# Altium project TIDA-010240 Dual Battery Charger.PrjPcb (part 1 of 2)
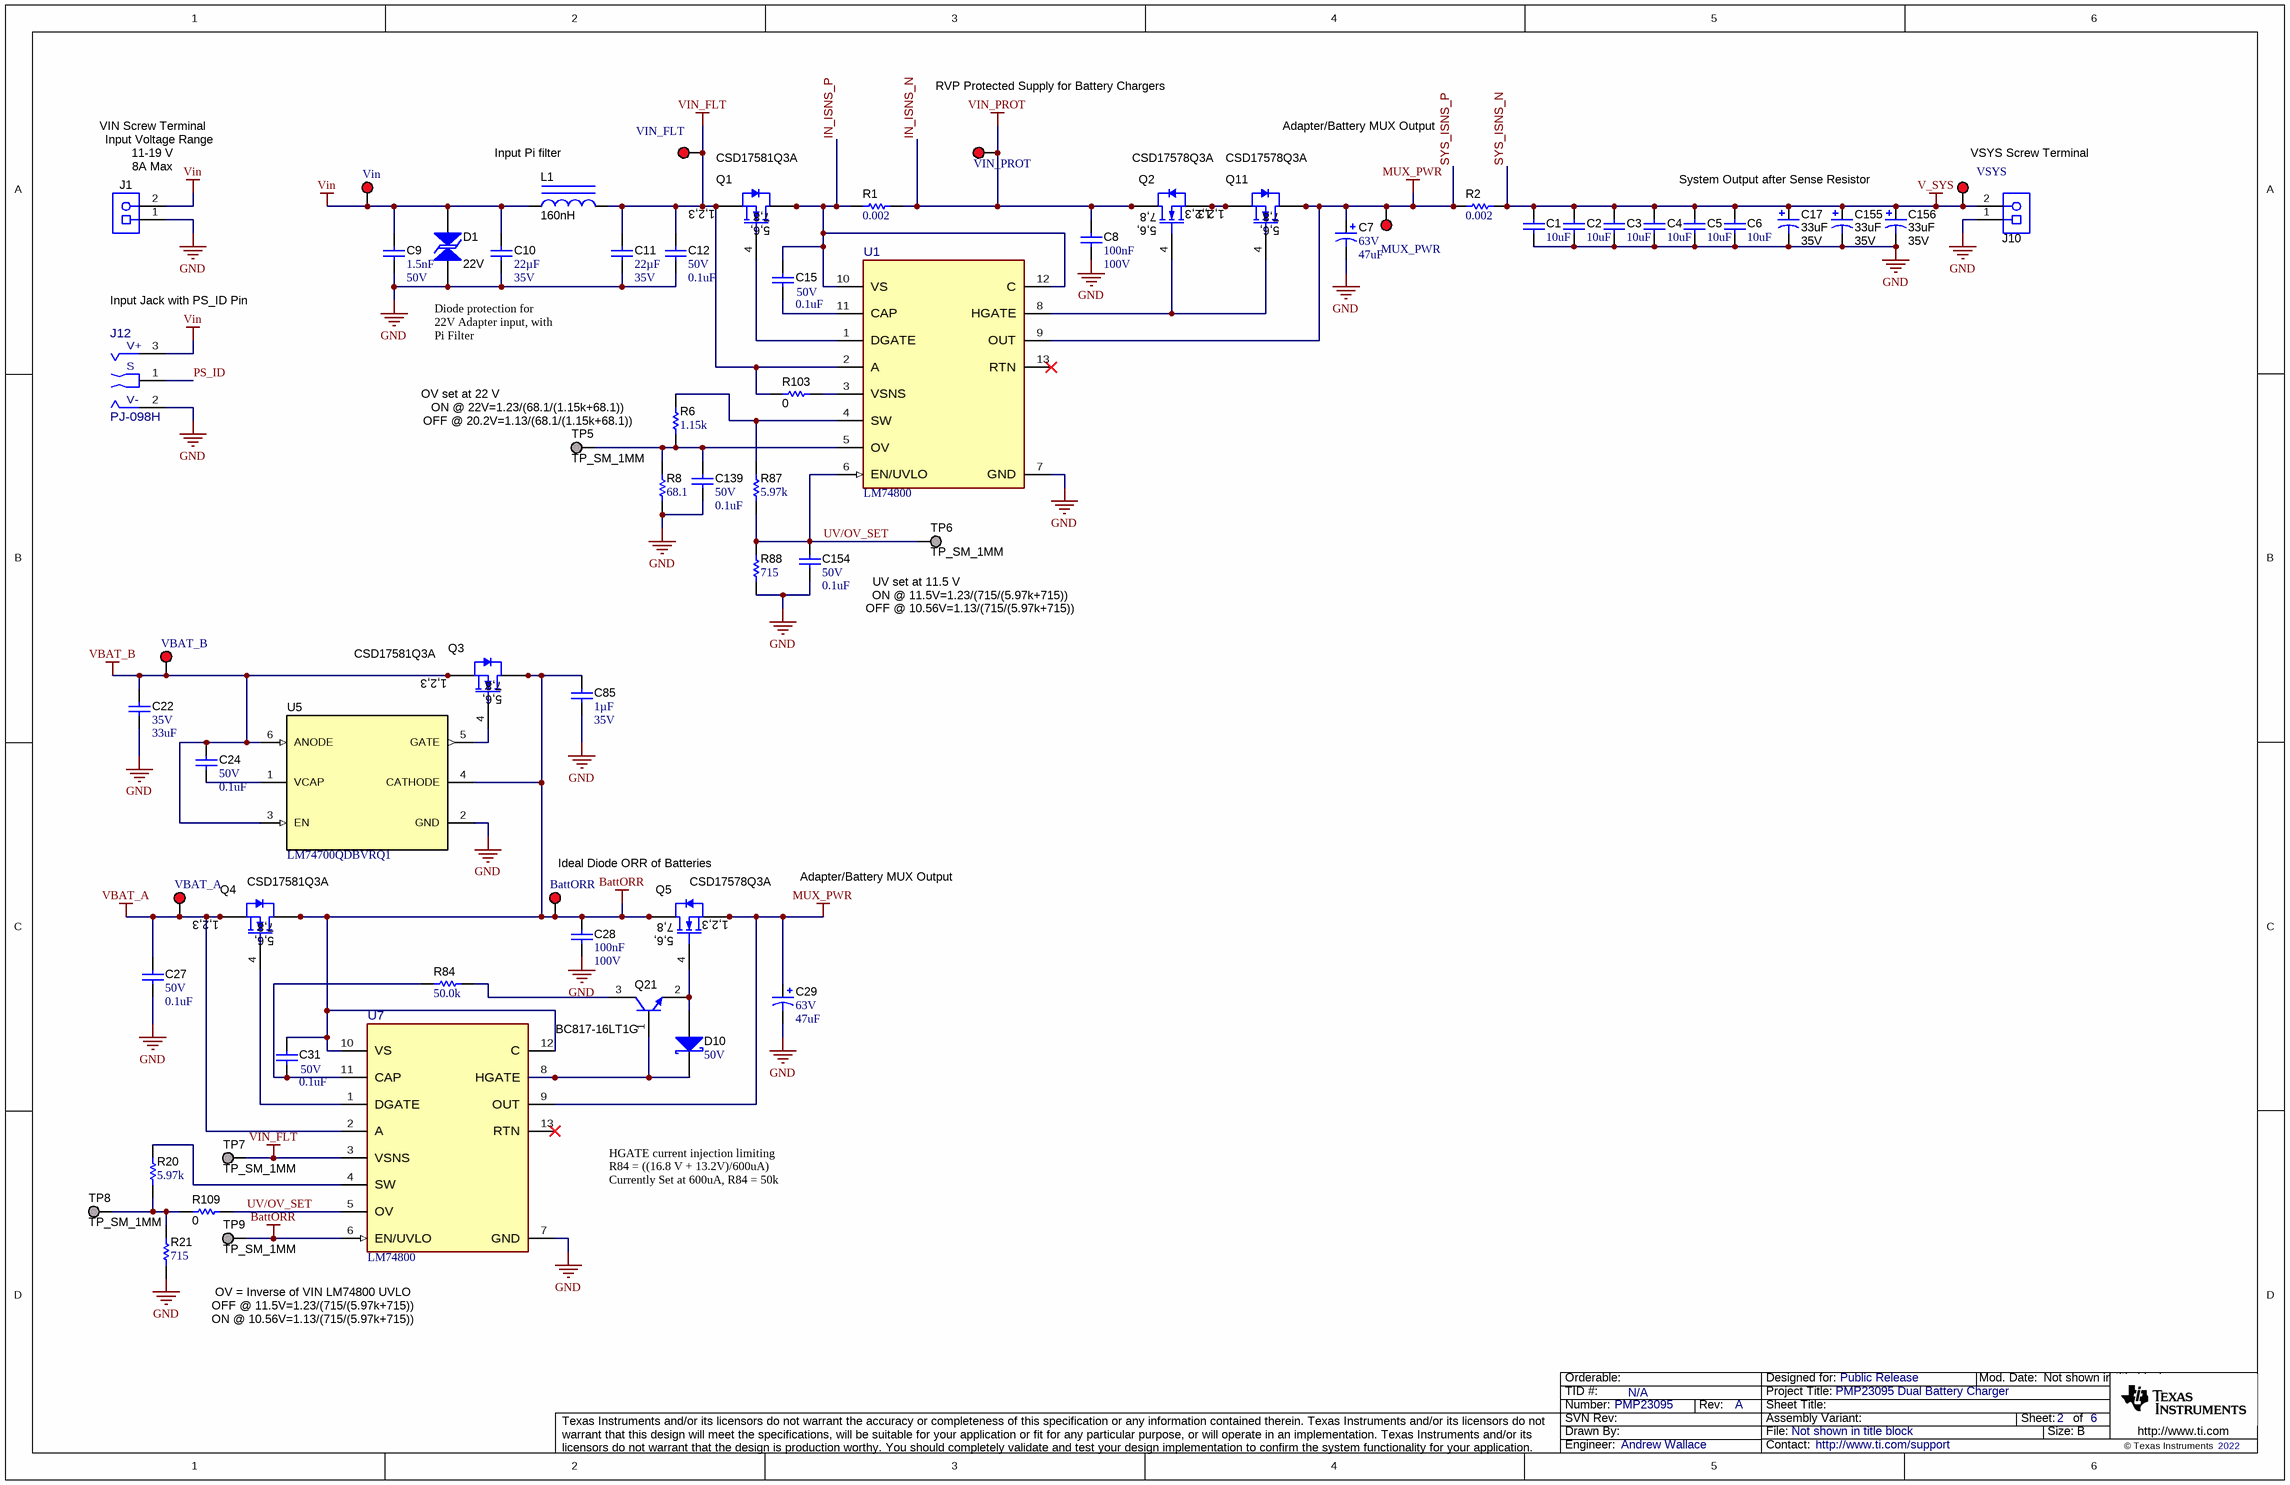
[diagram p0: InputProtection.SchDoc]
TID: N/A; TechSupport: http://www.ti.com/support; SCH_Rev: A; PRJ_Title: PMP23095 Dual Battery Charger; PRJ_Number: PMP23095; PRJ_Engineer: Andrew Wallace; PRJ_Customer: Public Release; PCB_Rev: A; PCB_Layout: Andrew Wallace; CopyrightYear: 2022
6 sheets, 371 parts. Net scope: global (net labels, ports and power ports of the same name join across sheets).
Board file: PCB_Project.PcbDoc
Sheets:
  InputProtection.SchDoc
  PCB_Project_Hardware.SchDoc
  MSP.SchDoc
  BQ25731_A.SchDoc
  BQ25731_B.SchDoc
  Sensing.SchDoc

## Sheet InputProtection.SchDoc
size 431 x 279 mm; Date: Not shown in title block; ApprovedBy: Not shown in title block; CheckedBy: Not shown in title block; Author: Not shown in title block; CompanyName: Not shown in title block; Engineer: Not shown in title block; Organization: Not shown in title block; Address1: Not shown in title block; Address2: Not shown in title block; Address3: Not shown in title block; Address4: Not shown in title block; DocumentNumber: 2; Revision: Use project parameter SCH_Rev; SheetNumber: 2; SheetTotal: 6; PageSetup: Record=PageOptions¦CenterHorizontal=True¦CenterVertical=True¦PrintScale=1.00¦XCorrection=1.00¦YCorrection=1.00¦PrintKind=0¦BorderSize=5000000¦LeftOffset=0¦BottomOffset=0¦Orientation=2¦PaperLength=1000¦PaperWidth=1000¦Scale=100¦PaperSource=15¦PrintQuality=600¦MediaType=1¦DitherType=10¦PaperKind=Letter¦PrintScaleMode=1

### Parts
BattORR  5010  [Keystone5010]  (value not drawn)
C1  ValueDisplayed: 10uF  [0805L]  (hidden comment: GRM21BR6YA106KE43L)
C2  ValueDisplayed: 10uF  [0805L]  (hidden comment: GRM21BR6YA106KE43L)
C3  ValueDisplayed: 10uF  [0805L]  (hidden comment: GRM21BR6YA106KE43L)
C4  ValueDisplayed: 10uF  [0805L]  (hidden comment: GRM21BR6YA106KE43L)
C5  ValueDisplayed: 10uF  [0805L]  (hidden comment: GRM21BR6YA106KE43L)
C6  ValueDisplayed: 10uF  [0805L]  (hidden comment: GRM21BR6YA106KE43L)
C7  VDC_V: 63V  ValueDisplayed: 47uF  [CAPSMT_62_HA0]  (hidden comment: EMVA630ADA470MHA0G)
C8  Cap_F: 100nF  VDC_V: 100V  [0603]  (hidden comment: GRM188R72A104KA35J)
C9  Cap_F: 1.5nF  VDC_V: 50V  [0603]  (hidden comment: GRM188R71H152KA01D)
C10  Cap_F: 22µF  VDC_V: 35V  [0805_HV]  (hidden comment: NMC0805X5R226M35TRPLPF)
C11  Cap_F: 22µF  VDC_V: 35V  [0805_HV]  (hidden comment: NMC0805X5R226M35TRPLPF)
C12  VDC_V: 50V  ValueDisplayed: 0.1uF  [0402]  (hidden comment: GCM155R71H104KE02D)
C15  VDC_V: 50V  ValueDisplayed: 0.1uF  [0402]  (hidden comment: GCM155R71H104KE02D)
C17  ValueDisplayed: 33uF  VDC_V: 35V  [7343-31]  (hidden comment: T521D336M035ATE065)
C22  VDC_V: 35V  ValueDisplayed: 33uF  [KCM55W]  (hidden comment: KCM55WR7YA336MH01K)
C24  VDC_V: 50V  ValueDisplayed: 0.1uF  [0402]  (hidden comment: GCM155R71H104KE02D)
C27  VDC_V: 50V  ValueDisplayed: 0.1uF  [0402]  (hidden comment: GCM155R71H104KE02D)
C28  Cap_F: 100nF  VDC_V: 100V  [0603]  (hidden comment: GRM188R72A104KA35J)
C29  VDC_V: 63V  ValueDisplayed: 47uF  [CAPSMT_62_HA0]  (hidden comment: EMVA630ADA470MHA0G)
C31  VDC_V: 50V  ValueDisplayed: 0.1uF  [0402]  (hidden comment: GCM155R71H104KE02D)
C85  Cap_F: 1µF  VDC_V: 35V  [0603]  (hidden comment: CGA3E1X7R1V105K080AC)
C139  VDC_V: 50V  ValueDisplayed: 0.1uF  [0402]  (hidden comment: GCM155R71H104KE02D)
C154  VDC_V: 50V  ValueDisplayed: 0.1uF  [0402]  (hidden comment: GCM155R71H104KE02D)
C155  ValueDisplayed: 33uF  VDC_V: 35V  [7343-31]  (hidden comment: T521D336M035ATE065)
C156  ValueDisplayed: 33uF  VDC_V: 35V  [7343-31]  (hidden comment: T521D336M035ATE065)
D1  value 22V  [SMC_Bi]  (hidden comment: SMCJ22CA-TR)
D10  value 50V  [SMA]  (hidden comment: B150-13-F)
J1  Receptacle_2x1  [On-Shore_ED120_2DS]  (value not drawn)
J10  Receptacle_2x1  [On-Shore_ED120_2DS]  (value not drawn)
J12  PJ-098H  [FP-PJ-098H_PTH_CONN_8MM0_12MM0-MFG]
L1  ValueDisplayed: 160nH  [WE-HCM_7070]  (hidden comment: 744307016)
MUX_PWR  5010  [Keystone5010]  (value not drawn)
Q1  CSD17581Q3A  [DNH0008A]
Q2  CSD17578Q3A  [DNH0008A]
Q3  CSD17581Q3A  [DNH0008A]
Q4  CSD17581Q3A  [DNH0008A]
Q5  CSD17578Q3A  [DNH0008A]
Q11  CSD17578Q3A  [DNH0008A]
Q21  BC817-16LT1G  [SOT-23]
R1  ValueDisplayed: 0.002  [1206]  (hidden comment: PMR18EZPFV2L00)
R2  ValueDisplayed: 0.002  [1206]  (hidden comment: PMR18EZPFV2L00)
R6  ValueDisplayed: 1.15k  [0603]  (hidden comment: RT0603BRD071K15L)
R8  ValueDisplayed: 68.1  [0603]  (hidden comment: CRCW060368R1FKEA)
R20  ValueDisplayed: 5.97k  [0603]  (hidden comment: RT0603DRE075K97L)
R21  ValueDisplayed: 715  [0603]  (hidden comment: RC0603FR-07715RL)
R84  ValueDisplayed: 50.0k  [0603]  (hidden comment: RT0603DRE0753KL)
R87  ValueDisplayed: 5.97k  [0603]  (hidden comment: RT0603DRE075K97L)
R88  ValueDisplayed: 715  [0603]  (hidden comment: RC0603FR-07715RL)
R103  ValueDisplayed: 0  [0603]  (hidden comment: RMCF0603ZT0R00)
R109  ValueDisplayed: 0  [0603]  (hidden comment: RMCF0603ZT0R00)
TP5  TP_SM_1MM  [TP_SM_1MM]  (no BOM)
TP6  TP_SM_1MM  [TP_SM_1MM]  (no BOM)
TP7  TP_SM_1MM  [TP_SM_1MM]  (no BOM)
TP8  TP_SM_1MM  [TP_SM_1MM]  (no BOM)
TP9  TP_SM_1MM  [TP_SM_1MM]  (no BOM)
U1  LM74800  [DRR0012E-MFG]
U5  LM74700QDBVRQ1  [DBV0006A_N]
U7  LM74800  [DRR0012E-MFG]
VBAT_A  5010  [Keystone5010]  (value not drawn)
VBAT_B  5010  [Keystone5010]  (value not drawn)
Vin  5010  [Keystone5010]  (value not drawn)
VIN_FLT  5010  [Keystone5010]  (value not drawn)
VIN_PROT  5010  [Keystone5010]  (value not drawn)
VSYS  5010  [Keystone5010]  (value not drawn)

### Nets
BattORR: BattORR.1 C28.1 C31.1 C85.2 Q3.5(D) Q3.6(D) Q3.7(D) Q3.8(D) Q3.9(D) Q4.5(D) Q4.6(D) Q4.7(D) Q4.8(D) Q4.9(D) Q5.5(D) Q5.6(D) Q5.7(D) Q5.8(D) Q5.9(D) TP9.1 U5.4(CATHODE) U7.6(EN/UVLO) U7.10(VS) U7.12(C)
GND: C1.2 C2.2 C3.2 C4.2 C5.2 C6.2 C7.2(-) C8.2 C9.2 C10.2 C11.2 C12.2 C17.2(-) C22.2 C27.2 C28.2 C29.2(-) C85.1 C139.2 C154.2 C155.2(-) C156.2(-) D1.1 J1.1 J10.1 J12.2(V-) R8.1 R21.1 R88.1 U1.7(GND) U5.2(GND) U7.7(GND)
IN_ISNS_N: C8.1 Q2.5(D) Q2.6(D) Q2.7(D) Q2.8(D) Q2.9(D) R1.1 VIN_PROT.1  [also labelled VIN_PROT]
SYS_ISNS_N: C1.1 C2.1 C3.1 C4.1 C5.1 C6.1 C17.1(+) C155.1(+) C156.1(+) J10.2 R2.1 VSYS.1  [also labelled V_SYS]
SYS_ISNS_P: C7.1(+) C29.1(+) MUX_PWR.1 Q5.1(S) Q5.2(S) Q5.3(S) Q11.5(D) Q11.6(D) Q11.7(D) Q11.8(D) Q11.9(D) R2.2 U1.9(OUT) U7.9(OUT)  [also labelled MUX_PWR]
VBAT_A: C27.1 Q4.1(S) Q4.2(S) Q4.3(S) U7.2(A) VBAT_A.1
VBAT_B: C22.1 C24.1 Q3.1(S) Q3.2(S) Q3.3(S) U5.3(EN) U5.6(ANODE) VBAT_B.1
Vin: C9.1 C10.1 D1.2 J1.2 J12.3(V+) L1.1 Vin.1
VIN_FLT: C11.1 C12.1 L1.2 Q1.1(S) Q1.2(S) Q1.3(S) R103.1 TP7.1 U1.2(A) U7.3(VSNS) VIN_FLT.1
IN_ISNS_P: C15.1 Q1.5(D) Q1.6(D) Q1.7(D) Q1.8(D) Q1.9(D) R1.2 U1.10(VS) U1.12(C)
PS_ID: J12.1(S)
UV/OV_SET: C154.1 R87.1 R88.2 R109.2 TP6.1 U1.6(EN/UVLO) U7.5(OV)
NetC15_2: C15.2 U1.11(CAP)
NetC24_2: C24.2 U5.1(VCAP)
NetC31_2: C31.2 R84.1 U7.11(CAP)
NetC139_1: C139.1 R6.1 R8.2 TP5.1 U1.5(OV)
NetD10_1: D10.1(K) Q21.1(B) U7.8(HGATE)
NetD10_2: D10.2(A) Q5.4(G) Q21.2(E)
NetQ1_4: Q1.4(G) U1.1(DGATE)
NetQ2_1: Q2.1(S) Q2.2(S) Q2.3(S) Q11.1(S) Q11.2(S) Q11.3(S)
NetQ2_4: Q2.4(G) Q11.4(G) U1.8(HGATE)
NetQ3_4: Q3.4(G) U5.5(GATE)
NetQ4_4: Q4.4(G) U7.1(DGATE)
NetQ21_3: Q21.3(C) R84.2
NetR6_2: R6.2 R87.2 U1.4(SW)
NetR20_1: R20.1 R21.2 R109.1 TP8.1
NetR20_2: R20.2 U7.4(SW)
NetR103_2: R103.2 U1.3(VSNS)

Not connected (* = marked no-connect by the designer): U1 13(RTN)*; U7 13(RTN)*

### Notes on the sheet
- RVP Protected Supply for Battery Chargers
- (near J1) 11-19 V
- (near J1) 8A Max
- VIN Screw Terminal
- Input Voltage Range
- (near L1) Input Pi filter
- Adapter/Battery MUX Output
- VSYS Screw Terminal
- System Output after Sense Resistor
- Input Jack with PS_ID Pin
- Diode protection for 22V Adapter input, with Pi Filter
- OV set at 22 V
- (near TP5) OFF @ 20.2V=1.13/(68.1/(1.15k+68.1))
- ON @ 22V=1.23/(68.1/(1.15k+68.1))
- (near TP6) UV set at 11.5 V
- OFF @ 10.56V=1.13/(715/(5.97k+715))
- ON @ 11.5V=1.23/(715/(5.97k+715))
- Ideal Diode ORR of Batteries
- HGATE current injection limiting
  R84 = ((16.8 V + 13.2V)/600uA)
  Currently Set at 600uA, R84 = 50k
- OFF @ 11.5V=1.23/(715/(5.97k+715))
- OV = Inverse of VIN LM74800 UVLO
- ON @ 10.56V=1.13/(715/(5.97k+715))

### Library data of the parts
BattORR MUX_PWR VBAT_A VBAT_B Vin VIN_FLT VIN_PROT VSYS = CMP-0055147-1: Test Point, Multipurpose, Red, TH; Manufacturer: Keystone; CNHeader: FALSE; Green_Lifecycle: Active; Green_REACh: Passed; CT: TRUE; ContactFinish: Silver
C1-C6 = CMP-0008310-2: CAP, CERM, 10 uF, 35 V, +/- 10%, X5R, 0805; Manufacturer: MuRata; Polarized: N; Value: 10uF; U/M: EA; Cap_F: 10µF; Value1: Unknown; VDC_V: 35V; TaMin_C: -55°C; TaMax_C: 85°C; Cap_Case: 0805; SizeArea_mm2: 2.5; SizeAreaWB_mm2: 6.75; SizeX_mm: 2; SizeY_mm: 1.25; SizeZ_mm: 1.45; AEC Category: Q200
C7 C29 = CMP-0011255-3: CAP, AL, 47 uF, 63 V, +/- 20%, SMD; Manufacturer: Chemi-Con; TaMin_C: -40°C; Polarized: Y; SizeAreaWB_mm2: 106.09; Value1: Unknown; U/M: EA; Value: 47uF; TaMax_C: 85°C; SizeZ_mm: 10; SizeX_mm: 8.3; Cap_Case: HA0; SizeArea_mm2: 68.89; CompType: Capacitor; Cap_F: 47µF; IRMS_A: 130mA; AEC Category: Q200
C8 C28 = CMP-0007470-5: CAP, CERM, 0.1 uF, 100 V, +/- 10%, X7R, 0603; Manufacturer: MuRata; TaMin_C: -55°C; Polarized: N; SizeAreaWB_mm2: 4.68; Value1: Unknown; U/M: EA; Value: 0.1uF; TaMax_C: 125°C; SizeZ_mm: 1; SizeX_mm: 1.6; SizeY_mm: 0.8; SizeArea_mm2: 1.28; AEC Category: Q200
C9 = CMP-0007437-4: CAP, CERM, 1500 pF, 50 V, +/- 10%, X7R, 0603; Manufacturer: MuRata; TaMin_C: -55°C; Polarized: N; SizeAreaWB_mm2: 4.68; Value1: Unknown; U/M: EA; Value: 1500pF; TaMax_C: 125°C; SizeZ_mm: 1; SizeX_mm: 1.6; SizeY_mm: 0.8; SizeArea_mm2: 1.28; AEC Category: Q200
C10 C11 = CMP-0860267-1: CAP, CERM, 22 µF, 35 V,+/- 20%, X5R, 0805; Manufacturer: Arrow; TaMin_C: -55°C; Polarized: N; SizeAreaWB_mm2: 6.75; U/M: EA; Value: 22uF; TaMax_C: 85°C; SizeZ_mm: 1.45; SizeX_mm: 2; SizeY_mm: 1.25; Cap_Case: 0805; SizeArea_mm2: 2.5; AEC Category: Q200
C12 C15 C24 C27 C31 C139 C154 = CMP-0006356-2: CAP, CERM, 0.1 uF, 50 V, +/- 10%, X7R, AEC-Q200 Grade 1, 0402; Manufacturer: MuRata; TaMin_C: -55°C; SizeAreaWB_mm2: 3; Value1: Unknown; U/M: EA; SizeZ_mm: 0.6; SizeArea_mm2: 0.5; SizeX_mm: 1; AEC Category: Q200; TaMax_C: 125°C; AEC Qualified: Y; Cap_F: 100nF; Value: 0.1uF; Polarized: N
C17 C155 C156 = CMP-0011849-2: CAP, TA, 33 uF, 35 V, +/- 20%, 0.065 ohm, SMD; Manufacturer: Kemet; Polarized: Y; CompType: Capacitor; Value: 33uF; U/M: EA; Cap_F: 33µF; ESR_ohm: 0.065; IRMS_A: 1.9A; TaMin_C: -55°C; TaMax_C: 125°C; AEC Category: Q200; AEC Qualified: N; SizeAreaWB_mm2: 58.59; SizeArea_mm2: 31.39; SizeX_mm: 7.3; SizeY_mm: 4.3; SizeZ_mm: 3.1
C22 = CMP-0009478-2: CAP, CERM, 33 uF, 35 V, +/- 20%, X7R, Stacked 2220; Manufacturer: MuRata; TaMin_C: -55°C; Polarized: N; SizeAreaWB_mm2: 59.13; Value1: Unknown; U/M: EA; Value: 33uF; TaMax_C: 125°C; SizeZ_mm: 6.7; SizeX_mm: 6.1; SizeY_mm: 5.3; Cap_Case: 2220; SizeArea_mm2: 32.33; Cap_F: 33µF; AEC Category: Q200
C85 = CMP-0007067-4: CAP, CERM, 1 uF, 35 V, +/- 10%, X7R, AEC-Q200 Grade 1, 0603; Manufacturer: TDK; TaMin_C: -55°C; ESR_ohm: 5.522m; Polarized: N; SizeAreaWB_mm2: 4.68; Value1: 0.005522 ohm; U/M: EA; Value: 1uF; TaMax_C: 125°C; SizeZ_mm: 1; SizeX_mm: 1.6; SizeY_mm: 0.8; SizeArea_mm2: 1.28; AEC Qualified: Y; IRMS_A: 2.2162A; AEC Category: Q200
D1 = CMP-0085453-1: Diode, TVS, Bi, 22 V, 35.5 Vc, 1500 W, 44 A, SMC (No Polarity Mark); Manufacturer: STMicroelectronics; SizeArea_mm2: 46.846; SizeX_mm: 7.94; Vbr_Min: 24.4V; AEC Qualified: N; SizeAreaWB_mm2: 78.526; Ppk: 1.5kW; Ipp: 44A; RJA_CperW: 90; SizeY_mm: 5.9; Value1: 35.5V; SizeZ_mm: 2.62; AEC Category: Q101
D10 = CMP-0028387-2: Diode, Schottky, 50 V, 1 A, SMA; Manufacturer: Diodes Inc.; SizeArea_mm2: 16.3228; SizeX_mm: 5.59; Green_Lifecycle: Active; SizeAreaWB_mm2: 37.3428; Green_REACh: Passed; SizeY_mm: 2.92; Value1: 1A; SizeZ_mm: 2.87; AEC Category: Q101; TJmax_C: 150°C; Vf_V: 700mV; RJC_CperW: 20; Value2: 0.7V
J1 J10 = CMP-0074910-1: Terminal Block, 5.08 mm, 2x1, Brass, TH; PartNumber: ED120/2DS; Manufacturer: On-Shore Technology; U/M: EA; Cert_VDE: Y; CNHeader: False; Current_A: 15A; Green_Lifecycle: Not Set; Shrouded: N; Gender: Female; Green_REACh: Incomplete; Voltage_V: 300V; Row_Count: 1; Pitch_mm: 5.08; CT: True
J12 = CMP-0092549-1: Manufacturer: CUI Devices; ContactFinish: Gold,Nickel; Conn Orientation: Right Angle; SizeZ_mm: 6.71mm; Conn Gender: Female; Is Female: yes; Voltage_V: 24V; AEC Qualified: No; Current_A: 6.5A
L1 = CMP-0063904-1: Inductor, Shielded Drum Core, Ferrite, 160 nH, 29 A, 0.00033 ohm, SMD; Manufacturer: Wurth Elektronik; Isat: 41A @ 20% inductance drop; Irms: 29A @ 50C rise; Green_Lifecycle: Active; SizeAreaWB_mm2: 86.48; DCR_ohm: 330µ; Green_REACh: Passed; Value: 160nH; Imax_A: 29A; SizeZ_mm: 7.2; SizeX_mm: 7.4; SizeArea_mm2: 53.28; AEC Category: Q200
Q1 Q3 Q4 = CMP-0079500-2: MOSFET, N-CH, 30 V, 60 A, DNH0008A (VSONP-8); Alternate Manufacturer: None; Manufacturer: Texas Instruments; SizeZ_mm: 0.9; ChType: N; Value2: 20 nC; Value1: 0.0047 ohm; VdsMax_V: 30V; SizeX_mm: 3.3; Vgs_V: 20V; Value: 30V; Rdson45_ohm: 4.7m; SizeArea_mm2: 10.89; AEC Category: Q101; IdsMax_A: 60A; SizeAreaWB_mm2: 18.49; QgTyp_nC: 20; ChMode: Enhancement
Q2 Q5 Q11 = CMP-0000591-2: MOSFET, N-CH, 30 V, 14 A, DNH0008A (VSONP-8); Alternate Manufacturer: None; Manufacturer: Texas Instruments; SizeZ_mm: 0.9; ChType: N; Value2: 7.9 nC; Value1: 0.008; VdsMax_V: 30V; SizeX_mm: 3.3; Vgs_V: 20V; Value: 30V; Rdson45_ohm: 8.2m; SizeArea_mm2: 10.89; AEC Category: Q101; IdsMax_A: 14A; SizeAreaWB_mm2: 18.49; QgTyp_nC: 7.9; ChMode: Enhancement
Q21 = CMP-0000420-2: Transistor, NPN, 45 V, 0.5 A, SOT-23; Manufacturer: ON Semiconductor; TaMax_C: 150°C; Value2: 250; Value1: 0.5 A; Vcesat1_V: 700mV; SizeX_mm: 2.5; SizeY_mm: 3; TaMin_C: -65°C; IcRated_A: 500mA; CompType: BJT; SizeZ_mm: 1.1; Value: 45 V; SizeArea_mm2: 7.5; NPN: 1; Vceo_V: 45V; PNP: 0; AEC Category: Q101; SizeAreaWB_mm2: 14; U/M: EA
R1 R2 = CMP-0081623-1: RES, 0.002, 1%, 1 W, AEC-Q200 Grade 0, 1206; Manufacturer: Rohm; Value_Code: 2L000; SizeAreaWB_mm2: 10.92; SizeArea_mm2: 5.12; AEC Qualified: Y; AEC Category: Q200; Res_ohm: 2m; Value: 0.002; SizeZ_mm: 1.35; Green_REACh: Incomplete; TempCo: 100 ppm/C; AEC Grade: 0; Power_W: 1W; SizeY_mm: 1.6; Green_Lifecycle: Active; SizeX_mm: 3.2
R6 = CMP-0023872-3: RES, 1.15 k, 0.1%, 0.1 W, 0603; Manufacturer: Yageo America; Power_W: 100mW; TempCo: 25 ppm/C; Value_Code: 1k15; U/M: EA; Value: 1.15k; EIA_Code: E192; SizeX_mm: 1.6; SizeY_mm: 0.8; SizeZ_mm: 1; SizeArea_mm2: 1.28; Value2: 0.1W; VDC_V: 75V; AEC Category: Q200
R8 = CMP-0022553-1: RES, 68.1, 1%, 0.1 W, 0603; Manufacturer: Vishay-Dale; Power_W: 100mW; TempCo: 100 ppm/C; Value_Code: 68R1; U/M: EA; Value: 68.1; EIA_Code: E96; SizeX_mm: 1.6; SizeY_mm: 0.8; SizeZ_mm: 1; Value2: 0.1W; SizeArea_mm2: 1.28; VDC_V: 75V; AEC Category: Q200
R20 R87 = CMP-0025446-1: RES, 5.97 k, 0.5%, 0.1 W, 0603; Manufacturer: Yageo America; Power_W: 100mW; TempCo: 50 ppm/C; Value_Code: 5k97; U/M: EA; Value: 5.97k; EIA_Code: E192; SizeX_mm: 1.6; SizeY_mm: 0.8; SizeZ_mm: 1; Value2: 0.1W; SizeArea_mm2: 1.28; VDC_V: 75V; AEC Category: Q200
R21 R88 = CMP-0023258-5: RES, 715, 1%, 0.1 W, 0603; Manufacturer: Yageo; Power_W: 100mW; TempCo: 100 ppm/C; Value_Code: 715R; Value: 715; EIA_Code: E96; SizeX_mm: 1.6; SizeY_mm: 0.8; SizeZ_mm: 1; Value2: 0.1W; SizeArea_mm2: 1.28; AEC Qualified: N; VDC_V: 75V; AEC Category: Q200; SizeAreaWB_mm2: 4.68
R84 = CMP-0025394-1: RES, 53.0 k, 0.5%, 0.1 W, 0603; Manufacturer: Yageo America; Power_W: 100mW; TempCo: 50 ppm/C; Value_Code: 53k0; U/M: EA; Value: 50.0k; EIA_Code: E192; Res_ohm: 53k; SizeX_mm: 1.6; SizeY_mm: 0.8; SizeZ_mm: 1; Value2: 0.1W; SizeArea_mm2: 1.28; VDC_V: 75V; AEC Category: Q200
R103 R109 = CMP-0023343-3: RES, 0, 1%, 0.1 W, AEC-Q200 Grade 0, 0603; Manufacturer: Stackpole Electronics Inc; Power_W: 100mW; TempCo: ppm/C; U/M: EA; Value: 0; SizeX_mm: 1.6; SizeY_mm: 0.8; SizeZ_mm: 1; Value2: 0.1W; SizeArea_mm2: 1.28; AEC Qualified: Y; AEC Category: Q200
TP5-TP9 = CMP-0003825-1: 1mm Test Point, SMT; Manufacturer: Any
U1 U7 = CMP-0089212-1: Ideal Diode Controller with Load Dump Protection; Manufacturer: Texas Instruments; Number Of Outputs: 1; TJmax_C: +150°C; Standoff Height: 0mm; AEC Qualified: Yes; Max Supply Voltage: 65V; TaMin_C: -40°C; SizeZ_mm: 0.8mm; TaMax_C: +125°C; Nominal Supply Current: 428uA; AEC Grade: Grade 1; Min Supply Voltage: 3V
U5 = CMP-0013281-4: Low Iq Always ON Smart Diode Controller, DBV0006A (SOT-23-6); Alternate PartNumber: LM74700QDBVTQ1; Manufacturer: Texas Instruments; SizeZ_mm: 1.45; SizeX_mm: 2.8; SizeY_mm: 2.9; SizeArea_mm2: 8.12; CompType: IC; SizeAreaWB_mm2: 14.82; AEC Category: Q200; AEC Qualified: Y

## Sheet PCB_Project_Hardware.SchDoc
size 431 x 279 mm; Date: Not shown in title block; ApprovedBy: Not shown in title block; CheckedBy: Not shown in title block; Author: Not shown in title block; CompanyName: Not shown in title block; Engineer: Not shown in title block; Organization: Not shown in title block; Address1: Not shown in title block; Address2: Not shown in title block; Address3: Not shown in title block; Address4: Not shown in title block; DocumentNumber: 3; Revision: Use project parameter SCH_Rev; SheetNumber: 3; SheetTotal: 6; PageSetup: Record=PageOptions¦CenterHorizontal=True¦CenterVertical=True¦PrintScale=1.00¦XCorrection=1.00¦YCorrection=1.00¦PrintKind=0¦BorderSize=5000000¦LeftOffset=0¦BottomOffset=0¦Orientation=2¦PaperLength=1000¦PaperWidth=1000¦Scale=100¦PaperSource=15¦PrintQuality=600¦MediaType=1¦DitherType=10¦PaperKind=Letter¦PrintScaleMode=1
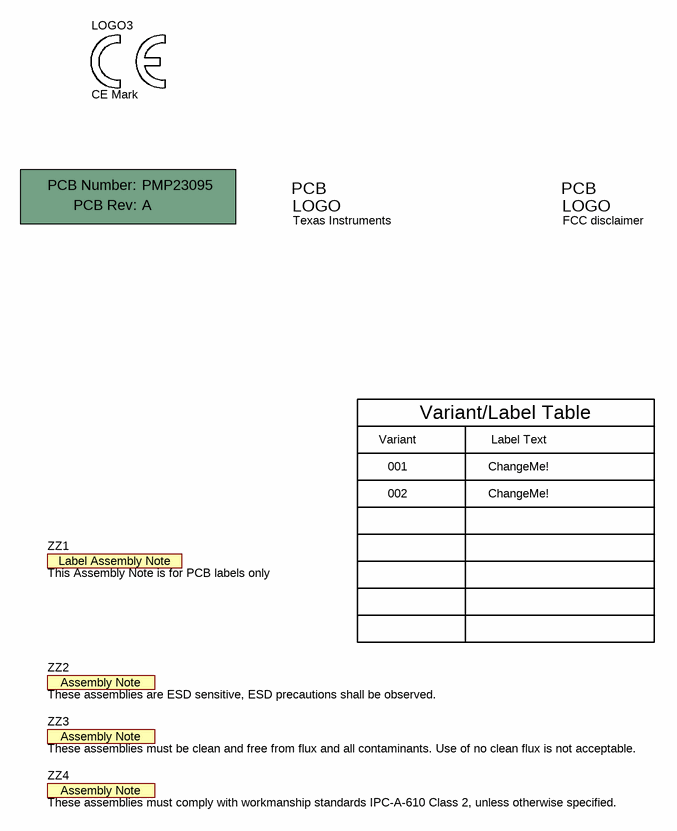
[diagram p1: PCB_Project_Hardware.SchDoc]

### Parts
!PCB1  Printed Circuit Board  (value not drawn)  (mechanical)
Logo1  Texas Instruments  [TI_Stacked_Overlay_Small]  (no BOM)
Logo2  FCC disclaimer  [FCC_disclaimer]  (no BOM)
LOGO3  CE Mark  [CE_Mark_5mm]  (no BOM)
ZZ1  This Assembly Note is for PCB labels only  [AssemblyNoteLabel]  (no BOM)
ZZ2  These assemblies are ESD sensitive, ESD precautions shall be observed.  [AssemblyNote]  (no BOM)
ZZ3  These assemblies must be clean and free from flux and all contaminants. Use of no clean flux is not acceptable.  [AssemblyNote]  (no BOM)
ZZ4  These assemblies must comply with workmanship standards IPC-A-610 Class 2, unless otherwise specified.  [AssemblyNote]  (no BOM)

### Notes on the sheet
- Variant
- Variant/Label Table
- Label Text
- 001
- 002
- ChangeMe!

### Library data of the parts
!PCB1 = CMP-0003618-2: Manufacturer: Any; PartNumber: PMP23095
Logo1 = CMP-0074838-1: Texas Instrument Corporate Signature; SymbolCreator: a0412235; Lib Reference: TI_Logo; Library Reference: Logo
Logo2 = CMP-0074847-1: FCC_disclaimer; Library Reference: Logo
LOGO3 = CMP-0074844-1: SymbolCreator: a0412235
ZZ1 = CMP-0003616-3
ZZ2 = CMP-0077236-1
ZZ3 = CMP-0077237-1
ZZ4 = CMP-0077238-1

## Sheet MSP.SchDoc
size 431 x 279 mm; Date: Not shown in title block; ApprovedBy: Not shown in title block; CheckedBy: Not shown in title block; Author: Not shown in title block; CompanyName: Not shown in title block; Engineer: Not shown in title block; Organization: Not shown in title block; Address1: Not shown in title block; Address2: Not shown in title block; Address3: Not shown in title block; Address4: Not shown in title block; DocumentNumber: 4; Revision: Use project parameter SCH_Rev; SheetNumber: 4; SheetTotal: 6; PageSetup: Record=PageOptions¦CenterHorizontal=True¦CenterVertical=True¦PrintScale=1.00¦XCorrection=1.00¦YCorrection=1.00¦PrintKind=0¦BorderSize=5000000¦LeftOffset=0¦BottomOffset=0¦Orientation=2¦PaperLength=1000¦PaperWidth=1000¦Scale=100¦PaperSource=15¦PrintQuality=600¦MediaType=1¦DitherType=10¦PaperKind=Letter¦PrintScaleMode=1
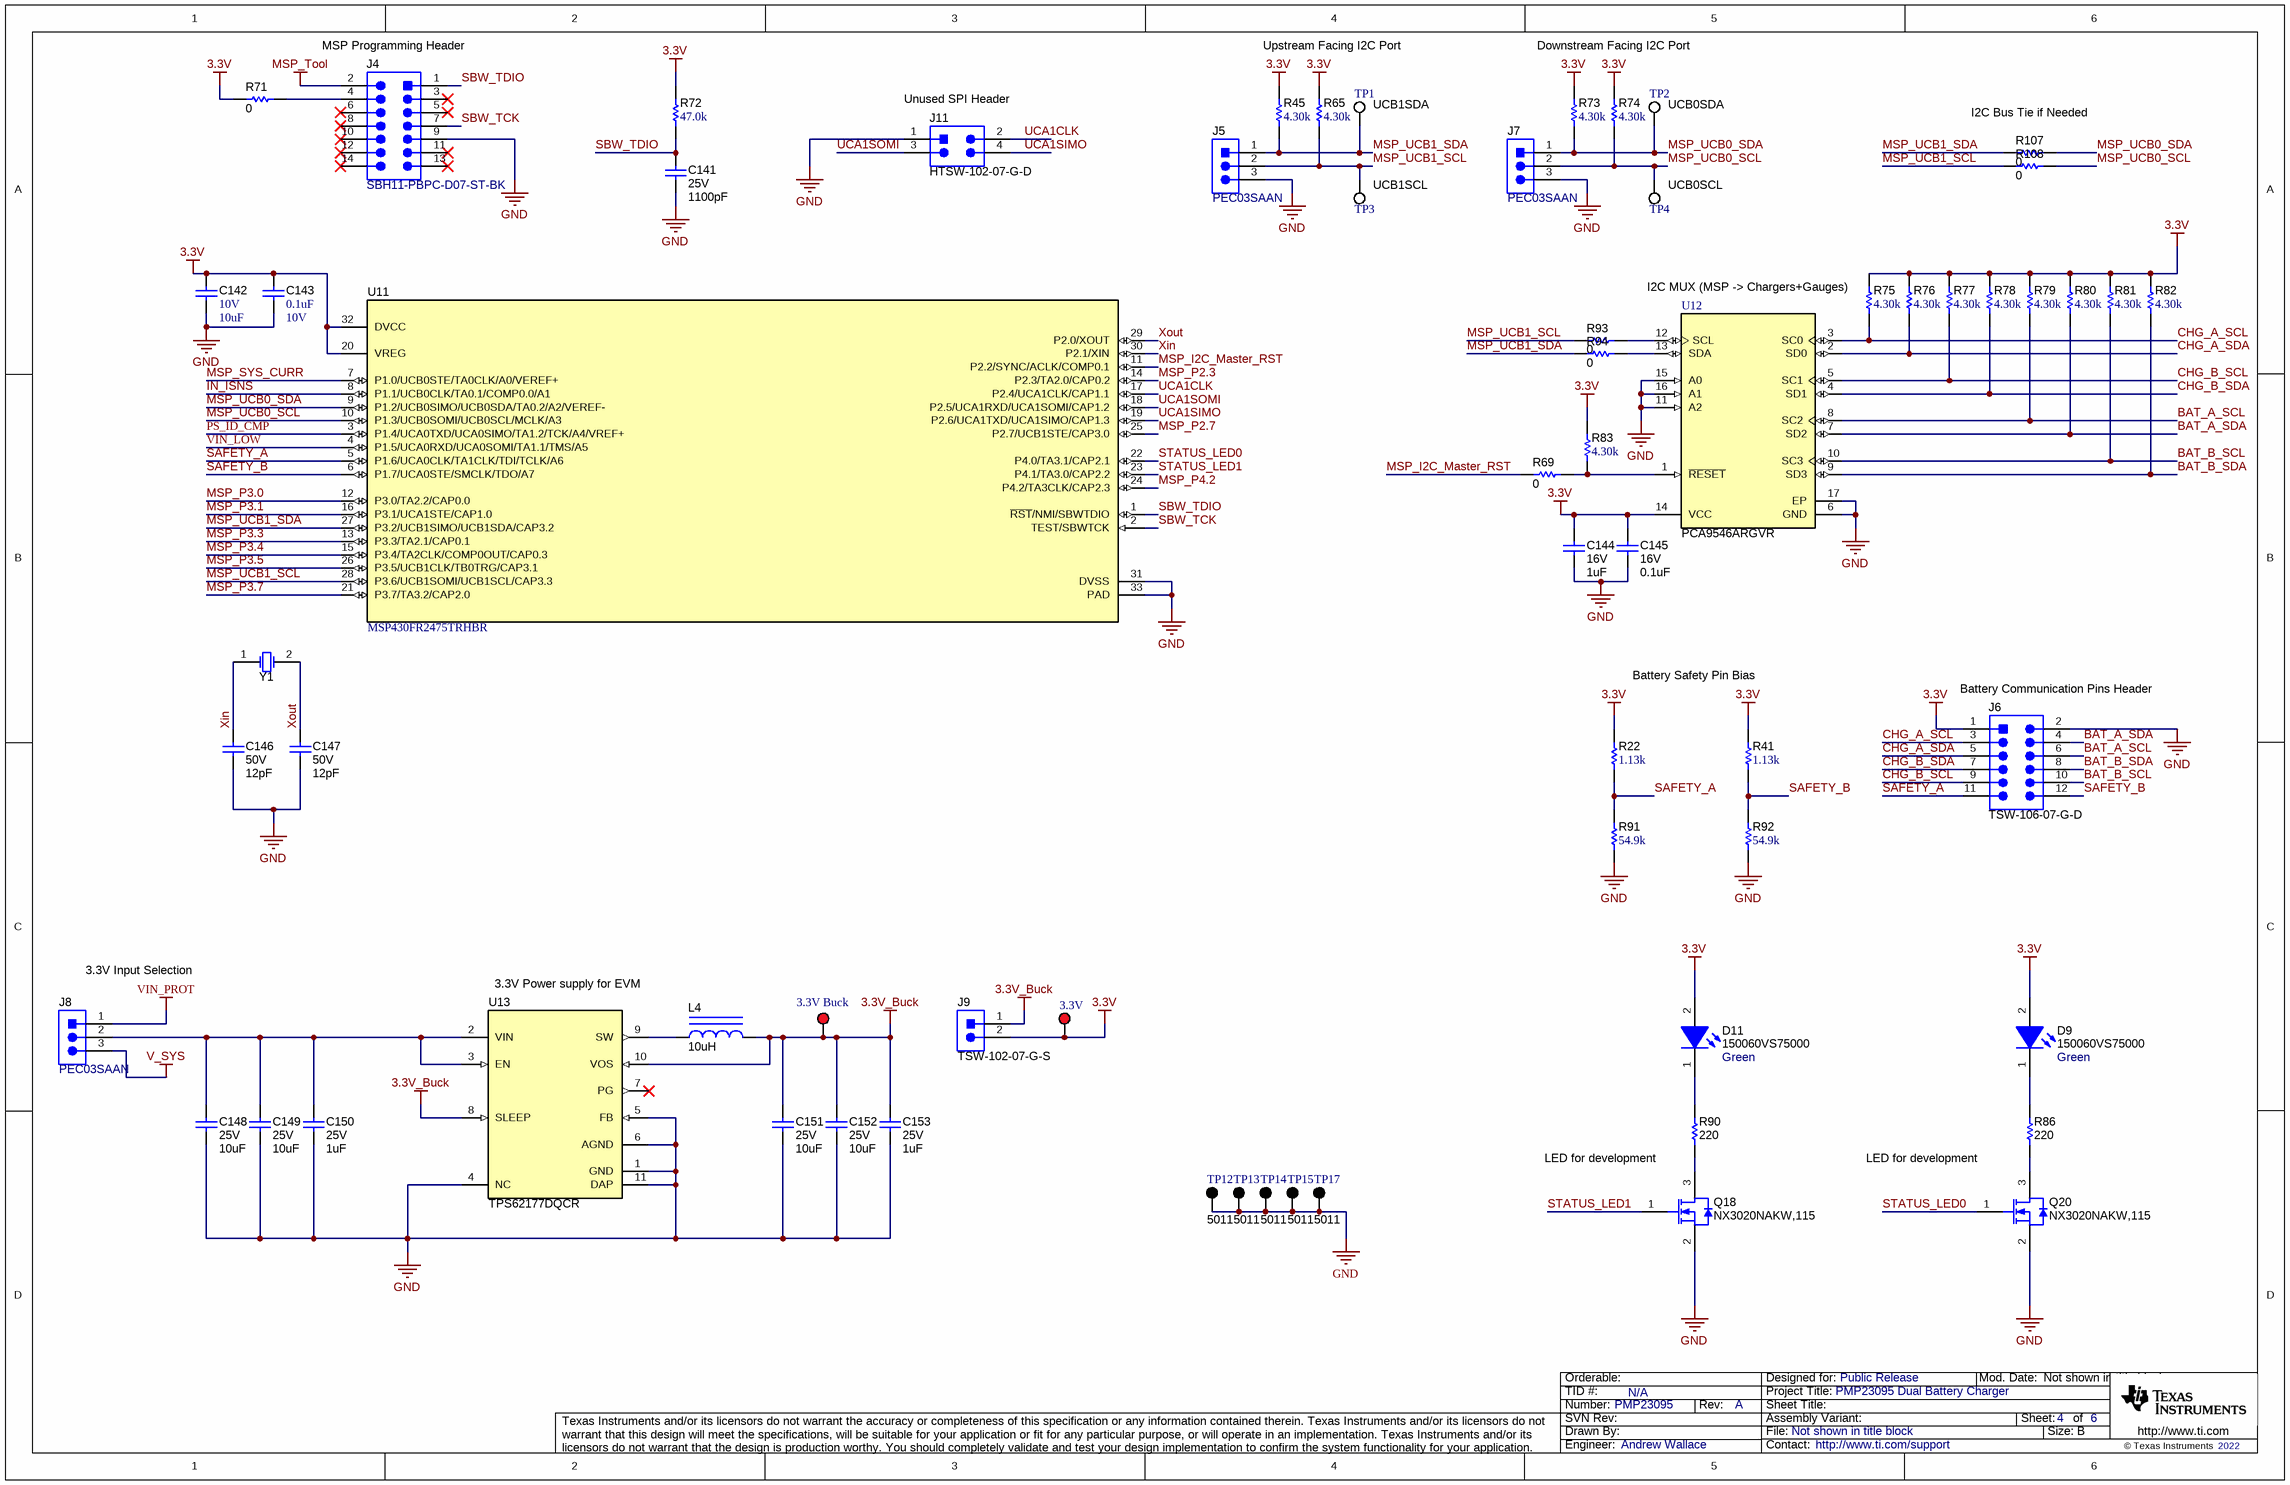
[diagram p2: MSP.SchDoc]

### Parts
3.3V  5010  [Keystone5010]  (value not drawn)
3.3V_Buck  5010  [Keystone5010]  (value not drawn)
C141  VDC_V: 25V  ValueDisplayed: 1100pF  [0603]  (hidden comment: GRM1885C1E112JA01D)
C142  VDC_V: 10V  ValueDisplayed: 10uF  [0603]  (hidden comment: GRM188Z71A106MA73D)
C143  ValueDisplayed: 0.1uF  VDC_V: 10V  [0603]  (hidden comment: C0603X104K8RACTU)
C144  VDC_V: 16V  ValueDisplayed: 1uF  [0603S]  (hidden comment: 885012106017)
C145  VDC_V: 16V  ValueDisplayed: 0.1uF  [0603S]  (hidden comment: GCM188R71C104KA37J)
C146  VDC_V: 50V  ValueDisplayed: 12pF  [0603S]  (hidden comment: 06035A120JAT2A)  (no BOM)
C147  VDC_V: 50V  ValueDisplayed: 12pF  [0603S]  (hidden comment: 06035A120JAT2A)  (no BOM)
C148  VDC_V: 25V  ValueDisplayed: 10uF  [0603S]  (hidden comment: C1608X5R1E106M080AC)
C149  VDC_V: 25V  ValueDisplayed: 10uF  [0603S]  (hidden comment: C1608X5R1E106M080AC)
C150  VDC_V: 25V  ValueDisplayed: 1uF  [0603S]  (hidden comment: C0603C105K3RACTU)
C151  VDC_V: 25V  ValueDisplayed: 10uF  [0603S]  (hidden comment: C1608X5R1E106M080AC)
C152  VDC_V: 25V  ValueDisplayed: 10uF  [0603S]  (hidden comment: C1608X5R1E106M080AC)
C153  VDC_V: 25V  ValueDisplayed: 1uF  [0603S]  (hidden comment: C0603C105K3RACTU)
D9  150060VS75000  value Green  [WL-SMCW_GREEN]
D11  150060VS75000  value Green  [WL-SMCW_GREEN]
J4  SBH11-PBPC-D07-ST-BK  [CONN_SBH11-PBPC-D07-ST-BK]
J5  PEC03SAAN  [CONN_PEC03SAAN]
J6  TSW-106-07-G-D  [TSW-106-07-G-D]
J7  PEC03SAAN  [CONN_PEC03SAAN]
J8  PEC03SAAN  [CONN_PEC03SAAN]
J9  TSW-102-07-G-S  [TSW-102-07-G-S]
J11  HTSW-102-07-G-D  [FP-HTSW-102-07-G-D_HDR4-MFG]
L4  ValueDisplayed: 10uH  [LPS4012]  (hidden comment: LPS4012-103MLB)
Q18  NX3020NAKW,115  [SOT-323]
Q20  NX3020NAKW,115  [SOT-323]
R22  ValueDisplayed: 1.13k  [0603]  (hidden comment: RT0603BRD071K13L)
R41  ValueDisplayed: 1.13k  [0603]  (hidden comment: RT0603BRD071K13L)
R45  ValueDisplayed: 4.30k  [0603]  (hidden comment: RC0603FR-074K3L)
R65  ValueDisplayed: 4.30k  [0603]  (hidden comment: RC0603FR-074K3L)
R69  ValueDisplayed: 0  [0603]  (hidden comment: RMCF0603ZT0R00)
R71  ValueDisplayed: 0  [0603]  (hidden comment: RMCF0603ZT0R00)
R72  ValueDisplayed: 47.0k  [0603]  (hidden comment: RC0603FR-0747KL)
R73  ValueDisplayed: 4.30k  [0603]  (hidden comment: RC0603FR-074K3L)
R74  ValueDisplayed: 4.30k  [0603]  (hidden comment: RC0603FR-074K3L)
R75  ValueDisplayed: 4.30k  [0603]  (hidden comment: RC0603FR-074K3L)
R76  ValueDisplayed: 4.30k  [0603]  (hidden comment: RC0603FR-074K3L)
R77  ValueDisplayed: 4.30k  [0603]  (hidden comment: RC0603FR-074K3L)
R78  ValueDisplayed: 4.30k  [0603]  (hidden comment: RC0603FR-074K3L)
R79  ValueDisplayed: 4.30k  [0603]  (hidden comment: RC0603FR-074K3L)
R80  ValueDisplayed: 4.30k  [0603]  (hidden comment: RC0603FR-074K3L)
R81  ValueDisplayed: 4.30k  [0603]  (hidden comment: RC0603FR-074K3L)
R82  ValueDisplayed: 4.30k  [0603]  (hidden comment: RC0603FR-074K3L)
R83  ValueDisplayed: 4.30k  [0603]  (hidden comment: RC0603FR-074K3L)
R86  ValueDisplayed: 220  [0603]  (hidden comment: RC0603FR-07220RL)
R90  ValueDisplayed: 220  [0603]  (hidden comment: RC0603FR-07220RL)
R91  ValueDisplayed: 54.9k  [0603]  (hidden comment: RT0603BRD0754K9L)
R92  ValueDisplayed: 54.9k  [0603]  (hidden comment: RT0603BRD0754K9L)
R93  ValueDisplayed: 0  [0603]  (hidden comment: RMCF0603ZT0R00)
R94  ValueDisplayed: 0  [0603]  (hidden comment: RMCF0603ZT0R00)
R107  ValueDisplayed: 0  [0603]  (hidden comment: RMCF0603ZT0R00)
R108  ValueDisplayed: 0  [0603]  (hidden comment: RMCF0603ZT0R00)
TP1  UCB1SDA  [Keystone5012]
TP2  UCB0SDA  [Keystone5012]
TP3  UCB1SCL  [Keystone5012]
TP4  UCB0SCL  [Keystone5012]
TP12  5011  [Keystone5011]
TP13  5011  [Keystone5011]
TP14  5011  [Keystone5011]
TP15  5011  [Keystone5011]
TP17  5011  [Keystone5011]
U11  MSP430FR2475TRHBR  [RHB0032E]
U12  PCA9546ARGVR  [RGV0016A]
U13  TPS62177DQCR  [DQC0010A]
Y1  ABS07-32.768KHZ-T  [XTAL_ABS07]  (value not drawn)  (no BOM)

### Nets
3.3V: 3.3V.1 C142.1 C143.1 C144.1 C145.1 D9.2(A) D11.2(A) J6.1 J9.2 R22.2 R41.2 R45.2 R65.2 R71.1 R72.2 R73.2 R74.2 R75.2 R76.2 R77.2 R78.2 R79.2 R80.2 R81.2 R82.2 R83.2 U11.20(VREG) U11.32(DVCC) U12.14(VCC)
3.3V_Buck: 3.3V_Buck.1 C151.1 C152.1 C153.1 J9.1 L4.2 U13.8(SLEEP) U13.10(VOS)
GND: C141.2 C142.2 C143.2 C144.2 C145.2 C146.2 C147.2 C148.2 C149.2 C150.2 C151.2 C152.2 C153.2 J4.9 J5.3 J6.2 J7.3 J11.1 Q18.2(S) Q20.2(S) R91.1 R92.1 TP12.1 TP13.1 TP14.1 TP15.1 TP17.1 U11.31(DVSS) U11.33(PAD) U12.6(GND) U12.11(A2) U12.15(A0) U12.16(A1) U12.17(EP) U13.1(GND) U13.4(NC) U13.5(FB) U13.6(AGND) U13.11(DAP)
MSP_Tool: J4.2
V_SYS: J8.3  [project net SYS_ISNS_N]
VIN_PROT: J8.1  [project net IN_ISNS_N]
BAT_A_SCL: J6.6 R79.1 U12.8(SC2)
BAT_A_SDA: J6.4 R80.1 U12.7(SD2)
BAT_B_SCL: J6.10 R81.1 U12.10(SC3)
BAT_B_SDA: J6.8 R82.1 U12.9(SD3)
CHG_A_SCL: J6.3 R75.1 U12.3(SC0)
CHG_A_SDA: J6.5 R76.1 U12.2(SD0)
CHG_B_SCL: J6.9 R77.1 U12.5(SC1)
CHG_B_SDA: J6.7 R78.1 U12.4(SD1)
IN_ISNS: U11.8(P1.1/UCB0CLK/TA0.1/COMP0.0/A1)
MSP_I2C_Master_RST: R69.1 U11.11(P2.2/SYNC/ACLK/COMP0.1)
MSP_P2.3: U11.14(P2.3/TA2.0/CAP0.2)
MSP_P2.7: U11.25(P2.7/UCB1STE/CAP3.0)
MSP_P3.0: U11.12(P3.0/TA2.2/CAP0.0)
MSP_P3.1: U11.16(P3.1/UCA1STE/CAP1.0)
MSP_P3.3: U11.13(P3.3/TA2.1/CAP0.1)
MSP_P3.4: U11.15(P3.4/TA2CLK/COMP0OUT/CAP0.3)
MSP_P3.5: U11.26(P3.5/UCB1CLK/TB0TRG/CAP3.1)
MSP_P3.7: U11.21(P3.7/TA3.2/CAP2.0)
MSP_P4.2: U11.24(P4.2/TA3CLK/CAP2.3)
MSP_SYS_CURR: U11.7(P1.0/UCB0STE/TA0CLK/A0/VEREF+)
MSP_UCB0_SCL: J7.2 R74.1 R108.2 TP4.1 U11.10(P1.3/UCB0SOMI/UCB0SCL/MCLK/A3)
MSP_UCB0_SDA: J7.1 R73.1 R107.2 TP2.1 U11.9(P1.2/UCB0SIMO/UCB0SDA/TA0.2/A2/VEREF-)
MSP_UCB1_SCL: J5.2 R65.1 R93.1 R108.1 TP3.1 U11.28(P3.6/UCB1SOMI/UCB1SCL/CAP3.3)
MSP_UCB1_SDA: J5.1 R45.1 R94.1 R107.1 TP1.1 U11.27(P3.2/UCB1SIMO/UCB1SDA/CAP3.2)
PS_ID_CMP: U11.3(P1.4/UCA0TXD/UCA0SIMO/TA1.2/TCK/A4/VREF+)
SAFETY_A: J6.11 R22.1 R91.2 U11.5(P1.6/UCA0CLK/TA1CLK/TDI/TCLK/A6)
SAFETY_B: J6.12 R41.1 R92.2 U11.6(P1.7/UCA0STE/SMCLK/TDO/A7)
SBW_TCK: J4.7 U11.2(TEST/SBWTCK)
SBW_TDIO: C141.1 J4.1 R72.1 U11.1(~{RST}/NMI/SBWTDIO)
STATUS_LED0: Q20.1(G) U11.22(P4.0/TA3.1/CAP2.1)
STATUS_LED1: Q18.1(G) U11.23(P4.1/TA3.0/CAP2.2)
UCA1CLK: J11.2 U11.17(P2.4/UCA1CLK/CAP1.1)
UCA1SIMO: J11.4 U11.19(P2.6/UCA1TXD/UCA1SIMO/CAP1.3)
UCA1SOMI: J11.3 U11.18(P2.5/UCA1RXD/UCA1SOMI/CAP1.2)
VIN_LOW: U11.4(P1.5/UCA0RXD/UCA0SOMI/TA1.1/TMS/A5)
Xin: C146.1 U11.30(P2.1/XIN) Y1.1(OSC1)
Xout: C147.1 U11.29(P2.0/XOUT) Y1.2(OSC2)
NetC148_1: C148.1 C149.1 C150.1 J8.2 U13.2(VIN) U13.3(EN)
NetD9_1: D9.1(K) R86.2
NetD11_1: D11.1(K) R90.2
NetJ4_4: J4.4 R71.2
NetL4_1: L4.1 U13.9(SW)
NetQ18_3: Q18.3(D) R90.1
NetQ20_3: Q20.3(D) R86.1
NetR69_2: R69.2 R83.1 U12.1(~{RESET})
NetR93_2: R93.2 U12.12(SCL)
NetR94_2: R94.2 U12.13(SDA)

Not connected (* = marked no-connect by the designer): J4 3* 5* 6* 8* 10* 11* 12* 13* 14*; U13 7(PG)*

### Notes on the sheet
- (near J4) MSP Programming Header
- (near J11) Unused SPI Header
- Upstream Facing I2C Port
- Downstream Facing I2C Port
- I2C Bus Tie if Needed
- (near R75) I2C MUX (MSP -> Chargers+Gauges)
- Battery Safety Pin Bias
- (near J6) Battery Communication Pins Header
- (near J8) 3.3V Input Selection
- 3.3V Power supply for EVM
- LED for development

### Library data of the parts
3.3V 3.3V_Buck = CMP-0055147-1: Test Point, Multipurpose, Red, TH; Manufacturer: Keystone; CNHeader: FALSE; Green_Lifecycle: Active; Green_REACh: Passed; ContactFinish: Silver; CT: TRUE
C141 = CMP-0007160-4: CAP, CERM, 1100 pF, 25 V, +/- 5%, C0G/NP0, 0603; Manufacturer: MuRata; TaMin_C: -55°C; Polarized: N; SizeAreaWB_mm2: 4.68; Value1: Unknown; U/M: EA; Value: 1100pF; TaMax_C: 125°C; SizeZ_mm: 1; SizeX_mm: 1.6; SizeY_mm: 0.8; SizeArea_mm2: 1.28; Cap_F: 1.1nF; AEC Category: Q200
C142 = CMP-0007497-5: CAP, CERM, 10 uF, 10 V, +/- 20%, X7R, 0603; Manufacturer: MuRata; TaMin_C: -55°C; Polarized: N; SizeAreaWB_mm2: 4.68; Value1: Unknown; U/M: EA; Value: 10uF; TaMax_C: 125°C; SizeZ_mm: 1; SizeX_mm: 1.6; SizeY_mm: 0.8; SizeArea_mm2: 1.28; Cap_F: 10µF; AEC Category: Q200
C143 = CMP-0006981-4: CAP, CERM, 0.1 uF, 10 V, +/- 10%, X7R, 0603; Manufacturer: Kemet; SizeAreaWB_mm2: 4.68; SizeArea_mm2: 1.28; SizeZ_mm: 1; Polarized: N; Cap_F: 100nF; TaMin_C: -55°C; AEC Category: Q200; SizeX_mm: 1.6; Value1: Unknown; Value: 0.1uF; U/M: EA; SizeY_mm: 0.8; TaMax_C: 125°C
C144 = CMP-0006824-5: CAP, CERM, 1 uF, 16 V, +/- 20%, X5R, 0603; Manufacturer: Wurth Elektronik; TaMin_C: -55°C; Polarized: N; SizeAreaWB_mm2: 4.68; Value1: Unknown; U/M: EA; Value: 1uF; TaMax_C: 85°C; SizeZ_mm: 1; SizeX_mm: 1.6; SizeY_mm: 0.8; Cap_Case: 0603; SizeArea_mm2: 1.28; Cap_F: 1µF; AEC Category: Q200
C145 = CMP-0007135-4: CAP, CERM, 0.1 uF, 16 V, +/- 10%, X7R, AEC-Q200 Grade 1, 0603; Manufacturer: MuRata; TaMin_C: -55°C; Polarized: N; SizeAreaWB_mm2: 4.68; Value1: Unknown; U/M: EA; Value: 0.1uF; TaMax_C: 125°C; SizeZ_mm: 1; SizeX_mm: 1.6; SizeY_mm: 0.8; Cap_Case: 0603; SizeArea_mm2: 1.28; AEC Qualified: Y; Cap_F: 100nF; AEC Category: Q200
C146 C147 = CMP-0006765-4: CAP, CERM, 12 pF, 50 V, +/- 5%, C0G/NP0, 0603; Manufacturer: AVX; TaMin_C: -55°C; ESR_ohm: 0.363; Polarized: N; SizeAreaWB_mm2: 4.68; Value1: 0.363 ohm; U/M: EA; Value: 12pF; TaMax_C: 125°C; SizeZ_mm: 1; SizeX_mm: 1.6; SizeY_mm: 0.8; Cap_Case: 0603; SizeArea_mm2: 1.28; AEC Category: Q200
C148 C149 C151 C152 = CMP-0007007-5: CAP, CERM, 10 uF, 25 V, +/- 20%, X5R, 0603; Manufacturer: TDK; TaMin_C: -55°C; ESR_ohm: 4.639m; Polarized: N; SizeAreaWB_mm2: 4.68; Value1: 0.004639 ohm; U/M: EA; Value: 10uF; TaMax_C: 85°C; SizeZ_mm: 1; SizeX_mm: 1.6; SizeY_mm: 0.8; Cap_Case: 0603; SizeArea_mm2: 1.28; Cap_F: 10µF; IRMS_A: 2.41407A; AEC Category: Q200
C150 C153 = CMP-0006867-4: CAP, CERM, 1 uF, 25 V, +/- 10%, X7R, 0603; Manufacturer: Kemet; TaMin_C: -55°C; Polarized: N; SizeAreaWB_mm2: 4.68; Value1: Unknown; U/M: EA; Value: 1uF; TaMax_C: 125°C; SizeZ_mm: 1; SizeX_mm: 1.6; SizeY_mm: 0.8; Cap_Case: 0603; SizeArea_mm2: 1.28; Cap_F: 1µF; AEC Category: Q200
D9 D11 = CMP-0002894-2: LED, Green, SMD; Manufacturer: Wurth Elektronik; Type: AlInGaP; Value2: 2V; Io_A: 20mA; Value1: W
J4 = CMP-0054695-2: Header (shrouded), 100 mil, 7x2, Gold, TH; Manufacturer: Sullins Connector Solutions; Green_REACh: Incomplete; Green_Lifecycle: Not Set
J5 J7 J8 = CMP-0002338-1: Header, 100mil, 3x1, Tin, TH; Manufacturer: Sullins Connector Solutions; CNHeader: TRUE; Current_A: 3A; Green_Lifecycle: Not Set; Shrouded: N; Gender: Male; Green_REACh: Incomplete; Voltage_V: 1.8kV; Row_Count: 1; Pitch_mm: 2.54; CT: FALSE; Cert_UL: Y
J6 = CMP-0075412-1: Header, 100mil, 6x2, Gold, TH; Manufacturer: Samtec; Pitch_mm: 2.54; Cert_VDE: N; Gender: Male; Cert_CSA: Y; Voltage_V: 550V; Green_REACh: Passed; Current_A: 6.3A; CT: False; Green_Lifecycle: Active; Row_Count: 2; CNHeader: True
J9 = CMP-0075405-2: Header, 100mil, 2x1, Gold, TH; Manufacturer: Samtec; Pitch_mm: 2.54; Cert_VDE: N; Gender: Male; Cert_CSA: Y; Voltage_V: 550V; Green_REACh: Passed; Current_A: 6.3A; Green_Lifecycle: Active; Row_Count: 1
J11 = CMP-0087344-2: Manufacturer: Samtec; Row_Count: 2; Voltage_V: 550V; Current_A: 6.3A; ContactFinish: Gold,Nickel
L4 = CMP-0060461-1: Inductor, Shielded Drum Core, Ferrite, 10 uH, 0.75 A, 0.35 ohm, SMD; Manufacturer: Coilcraft; Isat: 1.1A @ 30% inductance drop; Irms: 0.75A @ 40C rise; Green_Lifecycle: Not Set; SizeAreaWB_mm2: 25; DCR_ohm: 0.35; Green_REACh: Incomplete; Value: 10uH; Imax_A: 750mA; SizeZ_mm: 1.2; SizeX_mm: 4; Value2: 0.75A; SizeArea_mm2: 16; Ind_H: 10µH; AEC Category: Q200
Q18 Q20 = CMP-0000643-2: MOSFET, N-CH, 30 V, 0.18 A, SOT-323; Alternate Manufacturer: None; Manufacturer: Nexperia; SizeZ_mm: 1.1; ChType: N; Value2: 0.34 nC; Value1: 5; VdsMax_V: 30V; SizeX_mm: 2.2; Vgs_V: 20V; Value: 30V; Rdson45_ohm: 5.2; SizeArea_mm2: 4.84; AEC Category: Q101; IdsMax_A: 180mA; SizeAreaWB_mm2: 10.24; QgTyp_nC: 0.34
R22 R41 = CMP-0023870-1: RES, 1.13 k, 0.1%, 0.1 W, 0603; Manufacturer: Yageo America; Power_W: 100mW; TempCo: 25 ppm/C; Value_Code: 1k13; U/M: EA; Value: 1.13k; EIA_Code: E192; SizeX_mm: 1.6; SizeY_mm: 0.8; SizeZ_mm: 1; Value2: 0.1W; SizeArea_mm2: 1.28; VDC_V: 75V; AEC Category: Q200
R45 R65 R73-R83 = CMP-0023148-5: RES, 4.30 k, 1%, 0.1 W, 0603; Manufacturer: Yageo; Power_W: 100mW; TempCo: 100 ppm/C; Value_Code: 4k30; Value: 4.30k; Res_ohm: 4.3k; SizeX_mm: 1.6; SizeY_mm: 0.8; SizeZ_mm: 1; Value2: 0.1W; SizeArea_mm2: 1.28; AEC Qualified: N; VDC_V: 75V; AEC Category: Q200; SizeAreaWB_mm2: 4.68
R69 R71 R93 R94 R107 R108 = CMP-0023343-3: as R103 on sheet InputProtection
R72 = CMP-0023133-5: RES, 47.0 k, 1%, 0.1 W, 0603; Manufacturer: Yageo; Power_W: 100mW; TempCo: 100 ppm/C; Value_Code: 47k0; Value: 47.0k; Res_ohm: 47k; SizeX_mm: 1.6; SizeY_mm: 0.8; SizeZ_mm: 1; Value2: 0.1W; SizeArea_mm2: 1.28; AEC Qualified: N; VDC_V: 75V; AEC Category: Q200; SizeAreaWB_mm2: 4.68
R86 R90 = CMP-0022918-5: RES, 220, 1%, 0.1 W, 0603; Manufacturer: Yageo; Power_W: 100mW; TempCo: 100 ppm/C; Value_Code: 220R; Value: 220; SizeX_mm: 1.6; SizeY_mm: 0.8; SizeZ_mm: 1; Value2: 0.1W; SizeArea_mm2: 1.28; AEC Qualified: N; VDC_V: 75V; AEC Category: Q200; SizeAreaWB_mm2: 4.68
R91 R92 = CMP-0024334-3: RES, 54.9 k, 0.1%, 0.1 W, 0603; Manufacturer: Yageo America; Power_W: 100mW; TempCo: 25 ppm/C; Value_Code: 54k9; U/M: EA; Value: 54.9k; EIA_Code: E192; SizeX_mm: 1.6; SizeY_mm: 0.8; SizeZ_mm: 1; Value2: 0.1W; SizeArea_mm2: 1.28; VDC_V: 75V; AEC Category: Q200
TP1-TP4 = CMP-0055149-2: Test Point, Multipurpose, White, TH; Manufacturer: Keystone Electronics; ContactFinish: Silver; CT: TRUE; CNHeader: FALSE; Green_Lifecycle: Active; Green_REACh: Passed
TP12-TP15 TP17 = CMP-0055148-2: Test Point, Multipurpose, Black, TH; Manufacturer: Keystone Electronics; CNHeader: FALSE; ContactFinish: Silver; Green_REACh: Passed; Green_Lifecycle: Active; CT: TRUE
U11 = CMP-0081775-2: Mixed-Signal Microcontroller, RHB0032E (VQFN-32); Manufacturer: Texas Instruments; Alternate PartNumber: MSP430FR2475TRHBT; SizeAreaWB_mm2: 49; SizeArea_mm2: 25; AEC Qualified: N; AEC Category: Q200; SizeZ_mm: 1; SizeY_mm: 5; CompType: IC; Rating: Catalog
U12 = CMP-0043160-2: 4-Channel I2C and SMBus Multiplexer with Reset Functions, 2.3 to 5.5 V, -40 to 85 degC, 16-pin VQFN (RGV), Green (RoHS & no Sb/Br); Manufacturer: Texas Instruments; tpd max(ns): 0.3, 1; I2C Address: 1110 xxx; Reset Input: Yes; Max Frequency(kHz): 400; fSCLK(Max)(MHz): 100, 400; VCC(Max)(V): 5.5; Channel Width: 4; SubFamily: I2C Multiplexer, Switch; VCC(Min)(V): 2.3; Simultaneously Active Channels: 1 to 4
U13 = CMP-0067107-3: 28V, 0.5A Step-Down Converter with SNOOZE Mode, DQC0010A (WSON-10); Alternate PartNumber: TPS62177DQCT; Manufacturer: Texas Instruments; SizeZ_mm: 0.8; SizeX_mm: 2.0; SizeY_mm: 3.0; SizeArea_mm2: 6.0; CompType: IC; SizeAreaWB_mm2: 12.0
Y1 = CMP-0004628-3: CRYSTAL, 32.768KHz, 12.5PF, SMD; Manufacturer: Abracon Corporation; TaMin_C: -40°C; Frequency Stability: +/-20ppm; TaMax_C: 85°C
